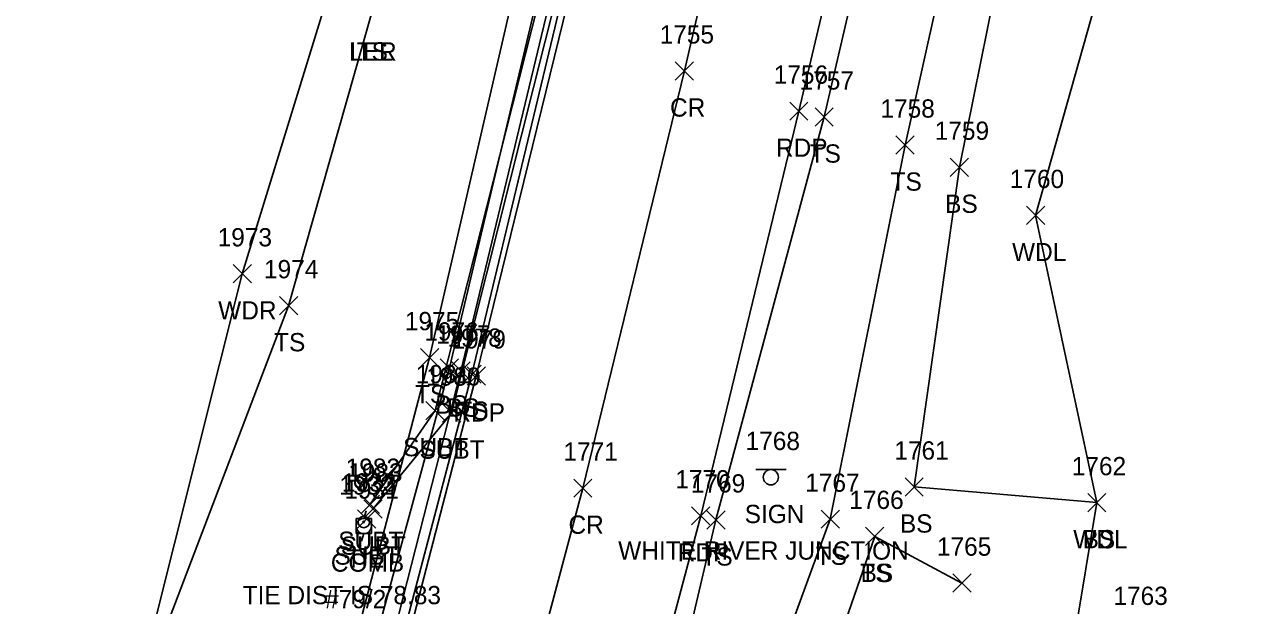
# Model space of a CAD drawing. Extents: x 1678863 to 1683592, y 407783 to 418211.
# Drawn here: x 1681072.9 to 1681208.1, y 416711.2 to 416774.8 of the extents above; entities that cross this region are included whole.
import ezdxf

# ---------------------------------------------------------------- set-up
doc = ezdxf.new("R2010")
doc.units = 0
for name, color, linetype in [('C_A', 7, 'Continuous'), ('C_C', 7, 'Continuous'), ('C_I', 7, 'Continuous'), ('CBP', 7, 'Continuous'), ('L_A', 7, 'Continuous'), ('L_I', 7, 'Continuous'), ('L_TIC', 7, 'Continuous'), ('LAWA', 7, 'Continuous'), ('LELB', 7, 'Continuous'), ('P_A', 7, 'Continuous'), ('P_I', 7, 'Continuous'), ('P_TIC', 7, 'Continuous'), ('PET', 7, 'Continuous'), ('PRC', 7, 'Continuous'), ('S_A', 7, 'Continuous'), ('S_C', 7, 'Continuous'), ('S_I', 7, 'Continuous'), ('SSGN', 7, 'Continuous'), ('U_A', 7, 'Continuous'), ('U_C', 7, 'Continuous'), ('U_I', 7, 'Continuous'), ('U_TIC', 7, 'Continuous'), ('UP', 7, 'Continuous'), ('UT', 7, 'Continuous')]:
    doc.layers.add(name, color=color, linetype=linetype)

msp = doc.modelspace()

# ---------------------------------------------------------------- linework, layer by layer
at = {"layer": 'CBP'}
for radius in [0.625, 0.0833]:
    msp.add_circle((1681110.04, 416720.31), radius, dxfattribs=at)
at = {"layer": 'L_TIC'}
for points in [[(1681159.43, 416763.66), (1681161.43, 416765.66)], [(1681161.43, 416763.66), (1681159.43, 416765.66)], [(1681168.29, 416760.59), (1681170.29, 416762.59)], [(1681170.29, 416760.59), (1681168.29, 416762.59)], [(1681174.23, 416758.16), (1681176.23, 416760.16)], [(1681176.23, 416758.16), (1681174.23, 416760.16)], [(1681182.57, 416752.88), (1681184.57, 416754.88)], [(1681184.57, 416752.88), (1681182.57, 416754.88)], [(1681095.75, 416746.49), (1681097.75, 416748.49)], [(1681097.75, 416746.49), (1681095.75, 416748.49)], [(1681100.82, 416743), (1681102.82, 416745)], [(1681102.82, 416743), (1681100.82, 416745)], [(1681116.24, 416737.31), (1681118.24, 416739.31)], [(1681118.24, 416737.31), (1681116.24, 416739.31)], [(1681118.42, 416736.18), (1681120.42, 416738.18)], [(1681120.42, 416736.18), (1681118.42, 416738.18)], [(1681119.67, 416735.84), (1681121.67, 416737.84)], [(1681121.67, 416735.84), (1681119.67, 416737.84)], [(1681120.88, 416735.5), (1681122.88, 416737.5)], [(1681122.88, 416735.5), (1681120.88, 416737.5)], [(1681169.28, 416723.15), (1681171.28, 416725.15)], [(1681171.28, 416723.15), (1681169.28, 416725.15)], [(1681189.27, 416721.43), (1681191.27, 416723.43)], [(1681191.27, 416721.43), (1681189.27, 416723.43)], [(1681189.27, 416721.43), (1681191.27, 416723.43)], [(1681191.27, 416721.43), (1681189.27, 416723.43)], [(1681147.59, 416719.54), (1681149.59, 416721.54)], [(1681149.59, 416719.54), (1681147.59, 416721.54)], [(1681160.1, 416719.62), (1681162.1, 416721.62)], [(1681162.1, 416719.62), (1681160.1, 416721.62)], [(1681164.97, 416717.74), (1681166.97, 416719.74)], [(1681166.97, 416717.74), (1681164.97, 416719.74)], [(1681164.97, 416717.74), (1681166.97, 416719.74)], [(1681166.97, 416717.74), (1681164.97, 416719.74)], [(1681174.51, 416712.62), (1681176.51, 416714.62)], [(1681176.51, 416712.62), (1681174.51, 416714.62)]]:
    msp.add_lwpolyline(points, dxfattribs=at)
at = {"layer": 'LAWA'}
for points in [[(1681123.87, 416850.36), (1681112.64, 416799.22), (1681096.75, 416747.49), (1681084.37, 416698.19), (1681077.36, 416674.66), (1681068.03, 416641.07), (1681060.5, 416598.12), (1681043.04, 416553.97), (1681032.51, 416518.11), (1681015.3, 416470.5), (1680994.93, 416429.19), (1680981.71, 416387.43), (1680969.09, 416365.63), (1680956.12, 416364.06)], [(1681197.88, 416804.7), (1681183.57, 416753.88), (1681190.27, 416722.43), (1681186.67, 416700.64), (1681165.75, 416661.66), (1681170.52, 416645), (1681144.5, 416606.08), (1681123.59, 416556.3), (1681122.46, 416512.19), (1681113.73, 416485.31), (1681126.06, 416479.17)]]:
    msp.add_lwpolyline(points, dxfattribs=at)
at = {"layer": 'LELB'}
for points in [[(1681156.02, 416991.73), (1681158.77, 416971.49), (1681161.75, 416953.98), (1681162.32, 416941.7), (1681158.74, 416923.13), (1681154.13, 416896.13), (1681147.11, 416869.12), (1681139.06, 416835.21), (1681130.14, 416794.31), (1681117.24, 416738.31), (1681106.01, 416695.36), (1681091.21, 416662.1), (1681090.98, 416658.87), (1681087.69, 416633.91), (1681075.38, 416588.29), (1681061.37, 416548.02), (1681048.8, 416510.6), (1681032.11, 416466.02), (1681014.69, 416421.51), (1680996.26, 416391.39), (1680989.28, 416368.73)], [(1681149.59, 416868.75), (1681142.29, 416833.77), (1681132.86, 416793.93), (1681119.42, 416737.18), (1681108.02, 416695.19), (1681098.81, 416668.5), (1681096.71, 416664.36), (1681094.64, 416660.46), (1681094.42, 416657.6), (1681089.82, 416632.97), (1681078.07, 416587.72), (1681064.01, 416547.9), (1681051.02, 416509.29), (1681033.52, 416465.65), (1681016.06, 416420.72), (1681000.74, 416389.34), (1680998.23, 416385.31), (1680994.64, 416376.69), (1680989.07, 416359.69), (1680992.46, 416359.07)], [(1681151.67, 416868.54), (1681144.5, 416832.96), (1681135.35, 416792.9), (1681121.88, 416736.5), (1681110.76, 416694.17), (1681101.65, 416666.79), (1681092.29, 416632.17), (1681079.85, 416586.59), (1681065.82, 416547), (1681053.32, 416508.48), (1681036.07, 416464.79), (1681019.24, 416419.35), (1681003.42, 416376.29), (1680994.23, 416357.71)], [(1681150.8, 416868.4), (1681143.7, 416833.38), (1681134.26, 416793.51), (1681120.67, 416736.84), (1681109.84, 416694.34), (1681100.61, 416667.6), (1681097.91, 416664.11), (1681097.08, 416660.69), (1681095.87, 416657.34), (1681091.25, 416632.74), (1681078.98, 416587.43), (1681065.33, 416547.21), (1681052.09, 416508.6), (1681034.7, 416465.08), (1681017.14, 416420.01), (1681002.48, 416388.48), (1680999.77, 416381.75), (1680997.06, 416375.63), (1680992.46, 416359.07)], [(1681183.55, 416833.63), (1681182.26, 416826.66), (1681180.25, 416810.78), (1681169.29, 416761.59), (1681161.1, 416720.62), (1681142.83, 416670.76), (1681140.44, 416656.68), (1681135.09, 416652.62), (1681137.22, 416644.16), (1681128.95, 416609.13), (1681110.82, 416560.56), (1681097.95, 416523.26), (1681082.61, 416474.04), (1681065.03, 416423.77), (1681042.03, 416376.09), (1681025.29, 416329.55), (1681005.26, 416289.72), (1680988.66, 416250.32), (1680971.75, 416212.59), (1680955.51, 416173.95), (1680940.89, 416151.62), (1680938.9, 416140.82), (1680934.47, 416141.15), (1680931.74, 416141.56)], [(1681176.14, 416832.62), (1681170.47, 416807.9), (1681160.43, 416764.66), (1681148.59, 416720.54), (1681137.34, 416672.66), (1681130.15, 416651.97), (1681117.39, 416611.26), (1681103.18, 416565.19), (1681090.71, 416525.17), (1681074.97, 416476.31), (1681056.64, 416426.82), (1681038.03, 416377.84), (1681018.75, 416331.61)], [(1681208.05, 416808.98), (1681192.15, 416815.79), (1681188.57, 416832.91), (1681185.19, 416808.54), (1681175.23, 416759.16), (1681170.28, 416724.15), (1681190.27, 416722.43)], [(1681110.86, 416775.84), (1681101.82, 416744), (1681084.37, 416698.19)], [(1681165.97, 416718.74), (1681148.66, 416668.7), (1681146.23, 416653.37), (1681141.68, 416649.74), (1681142.8, 416644.03), (1681133.74, 416607.2)], [(1681175.51, 416713.62), (1681165.97, 416718.74)]]:
    msp.add_lwpolyline(points, dxfattribs=at)
at = {"layer": 'P_TIC'}
for points in [[(1681144.13, 416768.7), (1681146.13, 416770.7)], [(1681146.13, 416768.7), (1681144.13, 416770.7)], [(1681156.66, 416764.3), (1681158.66, 416766.3)], [(1681158.66, 416764.3), (1681156.66, 416766.3)], [(1681121.35, 416735.31), (1681123.35, 416737.31)], [(1681123.35, 416735.31), (1681121.35, 416737.31)], [(1681133.02, 416723.02), (1681135.02, 416725.02)], [(1681135.02, 416723.02), (1681133.02, 416725.02)], [(1681145.92, 416719.99), (1681147.92, 416721.99)], [(1681147.92, 416719.99), (1681145.92, 416721.99)]]:
    msp.add_lwpolyline(points, dxfattribs=at)
at = {"layer": 'PET'}
for points in [[(1681153.18, 416868.37), (1681145.34, 416832.84), (1681136.15, 416792.61), (1681122.35, 416736.31), (1681111.4, 416694.04), (1681103.69, 416666.47), (1681093.64, 416631.55), (1681079.85, 416586.59), (1681067.41, 416546.57), (1681053.93, 416508), (1681038.48, 416463.96), (1681021.16, 416418.05), (1681004.81, 416375.74), (1680996.01, 416353.71), (1680982.81, 416321.51)], [(1681179.13, 416866.45), (1681171.86, 416831.02), (1681167.77, 416808.05), (1681157.66, 416765.3), (1681146.92, 416720.99), (1681134.47, 416674.25), (1681128.07, 416652.5), (1681116.34, 416611.65), (1681102.21, 416565.8), (1681089.4, 416525.72), (1681072.85, 416477.14), (1681054.83, 416427.43), (1681035.74, 416378.53), (1681017.06, 416332.68)]]:
    msp.add_lwpolyline(points, dxfattribs=at)
at = {"layer": 'PRC'}
msp.add_lwpolyline([(1681167.36, 416870.15), (1681159.37, 416832.34), (1681154.72, 416812.12), (1681150.38, 416792.5), (1681145.13, 416769.7), (1681134.02, 416724.02), (1681121.77, 416677.97), (1681115.56, 416656.52), (1681103.82, 416615.54), (1681089.85, 416570.67), (1681076.6, 416529.35), (1681060.09, 416481.99), (1681042.51, 416432.25), (1681023.42, 416383.55), (1681004.96, 416337.97)], dxfattribs=at)
at = {"layer": 'SSGN'}
for p, q in [((1681152.94, 416726.05), (1681156.28, 416726.05)), ((1681154.59, 416725.21), (1681154.59, 416725.21))]:
    msp.add_line(p, q, dxfattribs=at)
msp.add_circle((1681154.59, 416725.21), 0.833, dxfattribs=at)
at = {"layer": 'U_TIC'}
for points in [[(1681116.85, 416731.51), (1681118.85, 416733.51)], [(1681118.85, 416731.51), (1681116.85, 416733.51)], [(1681118.65, 416731.24), (1681120.65, 416733.24)], [(1681120.65, 416731.24), (1681118.65, 416733.24)], [(1681109.75, 416721.26), (1681111.75, 416723.26)], [(1681111.75, 416721.26), (1681109.75, 416723.26)], [(1681110.04, 416720.73), (1681112.04, 416722.73)], [(1681112.04, 416720.73), (1681110.04, 416722.73)], [(1681109.35, 416719.64), (1681111.35, 416721.64)], [(1681111.35, 416719.64), (1681109.35, 416721.64)]]:
    msp.add_lwpolyline(points, dxfattribs=at)
at = {"layer": 'UP'}
for p, q in [((1681110.3, 416721.54), (1681110.05, 416720.7)), ((1681109.22, 416719.04), (1681109.22, 416720.7)), ((1681109.22, 416720.7), (1681110.88, 416720.7)), ((1681110.05, 416719.87), (1681110.05, 416719.87)), ((1681110.88, 416720.7), (1681110.88, 416719.04)), ((1681110.88, 416719.04), (1681109.22, 416719.04)), ((1681109.8, 416718.2), (1681110.05, 416719.04))]:
    msp.add_line(p, q, dxfattribs=at)
msp.add_circle((1681110.05, 416719.87), 0.833, dxfattribs=at)
at = {"layer": 'UT'}
for points in [[(1681168.62, 416963.2), (1681155, 416897.34), (1681133.39, 416793.96), (1681117.85, 416732.51), (1681110.75, 416722.26)], [(1681171.05, 416962.91), (1681158.03, 416895.59), (1681135, 416793.29), (1681119.65, 416732.24), (1681111.04, 416721.73)]]:
    msp.add_lwpolyline(points, dxfattribs=at)

# ---------------------------------------------------------------- texts
at = {"layer": 'C_A'}
msp.add_text('TIE', height=2, dxfattribs=at).set_placement((1681108.12, 416715.31))
at = {"layer": 'C_C'}
msp.add_text('TIE DIST IS 78.83', height=2, dxfattribs=at).set_placement((1681096.79, 416711.31))
at = {"layer": 'C_I'}
msp.add_text('1932', height=2, dxfattribs=at).set_placement((1681107.35, 416723.31))
at = {"layer": 'L_A'}
for s, p in [('LER', (1681108.44, 416770.84)), ('LEL', (1681108.49, 416770.84)), ('TS', (1681109.27, 416770.84)), ('TS', (1681158.84, 416759.66)), ('TS', (1681167.7, 416756.59)), ('BS', (1681173.67, 416754.16)), ('WDL', (1681180.99, 416748.88)), ('WDR', (1681094.11, 416742.49)), ('TS', (1681100.23, 416739)), ('TS', (1681115.65, 416733.31)), ('BS', (1681117.86, 416732.18)), ('BS', (1681119.11, 416731.84)), ('TS', (1681120.29, 416731.5)), ('BS', (1681168.72, 416719.15)), ('WDL', (1681187.69, 416717.43)), ('BS', (1681188.71, 416717.43)), ('TS', (1681147, 416715.54)), ('TS', (1681159.51, 416715.62)), ('TS', (1681164.38, 416713.74)), ('BS', (1681164.41, 416713.74))]:
    msp.add_text(s, height=2, dxfattribs=at).set_placement(p)
at = {"layer": 'L_I'}
for s, p in [('1757', (1681157.74, 416767.66)), ('1758', (1681166.59, 416764.59)), ('1759', (1681172.53, 416762.16)), ('1760', (1681180.74, 416756.88)), ('1973', (1681094.05, 416750.49)), ('1974', (1681099.12, 416747)), ('1975', (1681114.54, 416741.31)), ('1976', (1681116.67, 416740.18)), ('1977', (1681117.98, 416739.84)), ('1978', (1681119.19, 416739.5)), ('1761', (1681168.11, 416727.15)), ('1762', (1681187.53, 416725.43)), ('1762', (1681187.53, 416725.43)), ('1769', (1681145.84, 416723.54)), ('1767', (1681158.36, 416723.62)), ('1766', (1681163.18, 416721.74)), ('1766', (1681163.18, 416721.74)), ('1765', (1681172.77, 416716.62))]:
    msp.add_text(s, height=2, dxfattribs=at).set_placement(p)
at = {"layer": 'P_A'}
for s, p in [('CR', (1681143.56, 416764.7)), ('RDP', (1681155.15, 416760.3)), ('RDP', (1681119.84, 416731.31)), ('CR', (1681132.45, 416719.02)), ('RDP', (1681144.4, 416715.99))]:
    msp.add_text(s, height=2, dxfattribs=at).set_placement(p)
at = {"layer": 'P_I'}
for s, p in [('1755', (1681142.43, 416772.7)), ('1756', (1681154.91, 416768.3)), ('1979', (1681119.65, 416739.31)), ('1771', (1681131.89, 416727.02)), ('1770', (1681144.14, 416723.99))]:
    msp.add_text(s, height=2, dxfattribs=at).set_placement(p)
at = {"layer": 'S_A'}
msp.add_text('SIGN', height=2, dxfattribs=at).set_placement((1681151.73, 416720.19))
at = {"layer": 'S_C'}
msp.add_text('WHITE RIVER JUNCTION', height=2, dxfattribs=at).set_placement((1681137.89, 416716.19))
at = {"layer": 'S_I'}
msp.add_text('1768', height=2, dxfattribs=at).set_placement((1681151.83, 416728.19))
at = {"layer": 'U_A'}
for s, p in [('SUBT', (1681114.35, 416727.51)), ('SUBT', (1681116.14, 416727.24)), ('SUBT', (1681107.25, 416717.26)), ('SUBT', (1681107.53, 416716.73)), ('SUBT', (1681106.84, 416715.64)), ('COMB', (1681106.44, 416714.87))]:
    msp.add_text(s, height=2, dxfattribs=at).set_placement(p)
at = {"layer": 'U_C'}
msp.add_text('#79/2', height=2, dxfattribs=at).set_placement((1681105.81, 416710.87))
at = {"layer": 'U_I'}
for s, p in [('1981', (1681115.73, 416735.51)), ('1980', (1681116.87, 416735.24)), ('1982', (1681108.06, 416725.26)), ('1983', (1681108.34, 416724.73)), ('1933', (1681107.65, 416723.64)), ('1931', (1681107.92, 416722.87)), ('1763', (1681192.09, 416711.23))]:
    msp.add_text(s, height=2, dxfattribs=at).set_placement(p)

doc.saveas('drawing.dxf')
